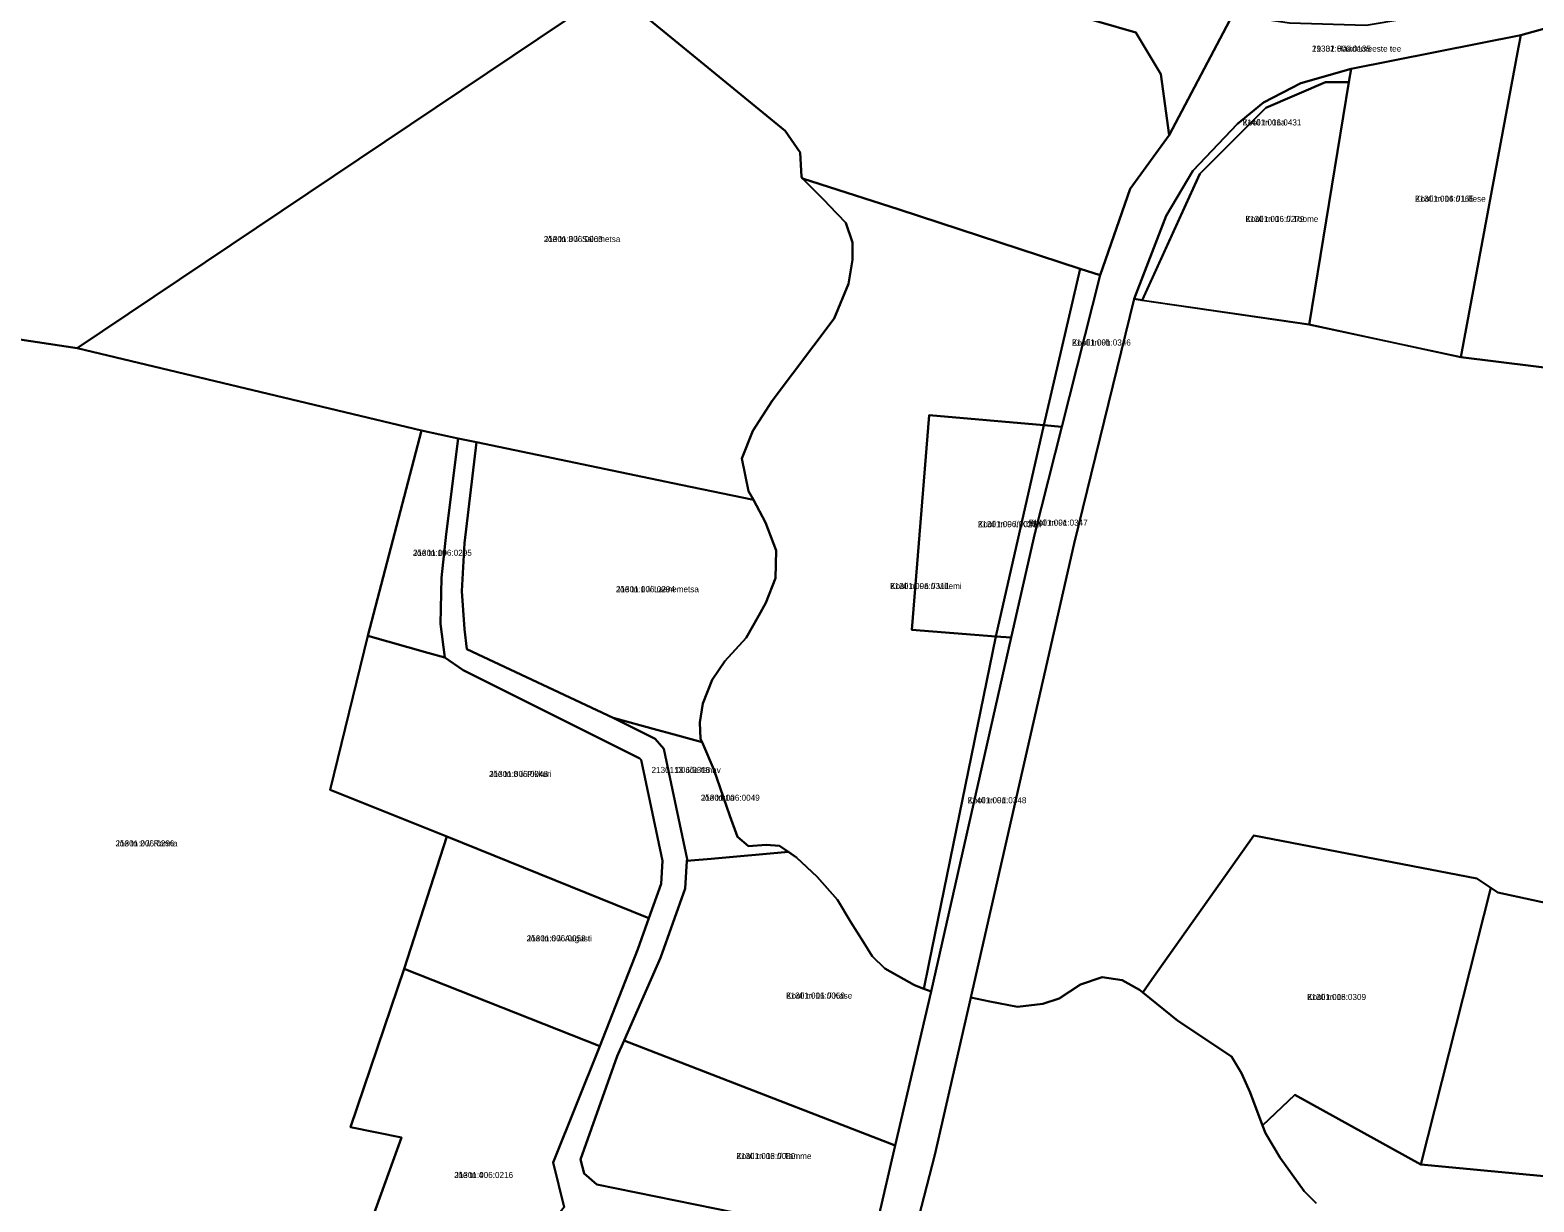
# Model space of a CAD drawing. Extents: x 520985 to 542706, y 6413723 to 6468993.
# Drawn here: x 528814.1 to 529184.5, y 6437370.3 to 6437658.9 of the extents above; entities that cross this region are included whole.
import ezdxf

# ---------------------------------------------------------------- set-up
doc = ezdxf.new("R2010")
doc.units = 0
for name, color, linetype in [('L_AADRESS', 7, 'Continuous'), ('PIIR', 7, 'Continuous'), ('TUNNUS', 7, 'Continuous')]:
    doc.layers.add(name, color=color, linetype=linetype)

msp = doc.modelspace()

# ---------------------------------------------------------------- linework, layer by layer
at = {"layer": 'PIIR'}
for points in [[(529022.94, 6437366.13), (529027.17, 6437384.16), (529036.06, 6437422.07), (529055.75, 6437509.24), (529061.56, 6437534.93), (529068.18, 6437561.14), (529077.63, 6437598.5), (529085.06, 6437619.76), (529094.63, 6437633.04), (529110.31, 6437662.71), (529124.29, 6437660.69), (529143.13, 6437660.13), (529162.25, 6437663.31), (529176.58, 6437665.99), (529231.94, 6437682.87)], [(528951.97, 6437665.27), (528825.68, 6437580.53), (528781.58, 6437587.19)], [(529068.18, 6437663.51), (529086.41, 6437658.27), (529092.59, 6437648.02), (529094.63, 6437633.04), (529085.06, 6437619.76), (529077.63, 6437598.5), (529072.76, 6437600.09), (529028.13, 6437614.73), (529004.35, 6437622.36), (529004.09, 6437622.7), (529003.78, 6437628.74), (529000.02, 6437634.04), (528962.09, 6437665.1)], [(529207.04, 6437664.8), (529181.26, 6437657.64), (529139.45, 6437649.35), (529127.06, 6437645.84), (529117.84, 6437641.01), (529111.48, 6437635.83), (529100.5, 6437624.23), (529093.87, 6437613.11), (529085.98, 6437592.65), (529071.25, 6437532.46), (529045.75, 6437420.61), (529036.91, 6437381.88), (529017.95, 6437308.4)], [(529110.31, 6437662.71), (529094.63, 6437633.04), (529092.59, 6437648.02), (529086.41, 6437658.27), (529068.18, 6437663.51)], [(529273.22, 6437425.26), (529175.58, 6437446.49), (529173.83, 6437447.63), (529170.46, 6437449.92), (529115.48, 6437460.49), (529090.38, 6437425.03), (529088.12, 6437421.84), (529087.32, 6437422.49), (529083.09, 6437424.88), (529078.15, 6437425.59), (529072.83, 6437423.84), (529067.56, 6437420.33), (529063.5, 6437419.05), (529057.25, 6437418.33), (529050.45, 6437419.63), (529045.75, 6437420.61), (529071.25, 6437532.46), (529085.98, 6437592.65), (529088, 6437592.36), (529129.01, 6437586.45), (529166.48, 6437578.36), (529202.94, 6437573.84)], [(528945.61, 6437368.99), (528942.95, 6437379.95), (528954.39, 6437408.63), (528963.75, 6437432.55), (528966.46, 6437440.14), (528969.5, 6437448.64), (528969.85, 6437454.26), (528964.59, 6437479.11), (528964.26, 6437479.49), (528920.74, 6437501.22), (528916.24, 6437504.33), (528915.15, 6437512.66), (528915.44, 6437523.97), (528916.57, 6437534.72), (528919.5, 6437558.33), (528924.06, 6437557.36), (528921.06, 6437532.5), (528920.43, 6437520.71), (528921.06, 6437511.35), (528921.65, 6437506.39), (528957.68, 6437489.5), (528968.01, 6437484.34), (528970.14, 6437481.86), (528975.9, 6437454.69), (528975.87, 6437454.26), (528975.43, 6437447.43), (528969.34, 6437430.34), (528960.4, 6437410.02), (528958.7, 6437406.14), (528949.67, 6437380.74), (528950.55, 6437377.24), (528953.69, 6437374.52), (529002.12, 6437364.71)], [(529017.95, 6437308.4), (529036.91, 6437381.88), (529045.75, 6437420.61), (529050.45, 6437419.63), (529057.25, 6437418.33), (529063.5, 6437419.05), (529067.56, 6437420.33), (529072.83, 6437423.84), (529078.15, 6437425.59), (529083.09, 6437424.88), (529087.32, 6437422.49), (529088.12, 6437421.84), (529096.74, 6437414.87), (529109.98, 6437406.05), (529112.49, 6437401.98), (529114.58, 6437397.18), (529117.66, 6437389.09), (529118.37, 6437387.22), (529121.96, 6437381.15), (529127.87, 6437372.94), (529130.87, 6437369.96)], [(529130.87, 6437369.96), (529127.87, 6437372.94), (529121.96, 6437381.15), (529118.37, 6437387.22), (529117.66, 6437389.09), (529125.57, 6437396.67), (529156.61, 6437379.48), (529244.98, 6437371.11), (529245.83, 6437371.03), (529171.7, 6437219.39)]]:
    msp.add_lwpolyline(points, dxfattribs=at)
for points in [[(528919.5, 6437558.33), (528910.48, 6437560.26), (528825.68, 6437580.53), (528951.97, 6437665.27), (528959.29, 6437670.18), (528962.09, 6437665.1), (529000.02, 6437634.04), (529003.78, 6437628.74), (529004.09, 6437622.7), (529004.35, 6437622.36), (529009.79, 6437616.82), (529010.88, 6437615.69), (529015, 6437611.4), (529016.65, 6437606.54), (529016.66, 6437602.33), (529015.63, 6437596.42), (529012.14, 6437587.86), (528996.85, 6437567.6), (528992.12, 6437560.18), (528989.42, 6437553.36), (528991.06, 6437545.29), (528992.23, 6437543.16), (528974.34, 6437546.88), (528924.06, 6437557.36)], [(529181.26, 6437657.64), (529207.04, 6437664.8), (529218.21, 6437668.23), (529217.82, 6437665.67), (529210.2, 6437615.42), (529202.94, 6437573.84), (529166.48, 6437578.36), (529180.71, 6437654.67)], [(529139.45, 6437649.35), (529181.26, 6437657.64), (529180.71, 6437654.67), (529166.48, 6437578.36), (529129.14, 6437586.29), (529138.91, 6437646.07)], [(529102.21, 6437623.47), (529087.98, 6437592.36), (529085.98, 6437592.65), (529093.87, 6437613.11), (529100.5, 6437624.23), (529111.48, 6437635.83), (529117.84, 6437641.01), (529127.06, 6437645.84), (529139.45, 6437649.35), (529138.91, 6437646.07), (529133.11, 6437646.05), (529118.48, 6437639.7)], [(529102.21, 6437623.47), (529118.48, 6437639.7), (529133.11, 6437646.05), (529138.91, 6437646.07), (529129.14, 6437586.29), (529087.95, 6437592.29)], [(529012.92, 6437444.63), (529007.91, 6437450.34), (529002.89, 6437455.13), (528998.65, 6437457.98), (528995.37, 6437458.18), (528991.03, 6437457.88), (528988.32, 6437460.22), (528986.4, 6437465.32), (528982.45, 6437476.73), (528979.58, 6437483.5), (528979.22, 6437484.35), (528979.07, 6437488.33), (528979.74, 6437493.06), (528982.05, 6437498.85), (528985.16, 6437503.45), (528990.47, 6437509.16), (528993.57, 6437514.73), (528995.3, 6437517.83), (528997.7, 6437523.88), (528997.84, 6437530.71), (528995.25, 6437537.57), (528992.23, 6437543.16), (528991.06, 6437545.29), (528989.42, 6437553.36), (528992.12, 6437560.18), (528996.85, 6437567.6), (529012.14, 6437587.86), (529015.63, 6437596.42), (529016.66, 6437602.33), (529016.65, 6437606.54), (529015, 6437611.4), (529010.88, 6437615.69), (529009.79, 6437616.82), (529004.35, 6437622.36), (529028.13, 6437614.73), (529072.76, 6437600.09), (529063.77, 6437561.61), (529035.54, 6437564.04), (529031.27, 6437511.14), (529051.96, 6437509.56), (529035.44, 6437428.81), (529034.19, 6437422.78), (529031.91, 6437423.66), (529024.57, 6437427.72), (529021.45, 6437430.77), (529019.38, 6437434.23), (529016.2, 6437439.13)], [(529072.76, 6437600.09), (529077.63, 6437598.5), (529068.18, 6437561.14), (529063.77, 6437561.61)], [(528763.29, 6437445.82), (528774.26, 6437528.12), (528775.61, 6437538.22), (528779.34, 6437571.35), (528780.07, 6437576.55), (528781.25, 6437584.93), (528781.58, 6437587.19), (528825.68, 6437580.53), (528910.48, 6437560.26), (528897.26, 6437509.7), (528888, 6437471.74), (528916.74, 6437460.23), (528906.2, 6437427.71), (528892.96, 6437388.69), (528905.53, 6437386.15), (528882.7, 6437322.88), (528881.29, 6437319.33), (528870.51, 6437323.67), (528753.51, 6437368.93), (528754.17, 6437373.73), (528758.2, 6437405.79)], [(529035.54, 6437564.04), (529063.77, 6437561.61), (529051.96, 6437509.56), (529031.27, 6437511.14)], [(528910.48, 6437560.26), (528919.5, 6437558.33), (528916.57, 6437534.72), (528915.44, 6437523.97), (528915.15, 6437512.66), (528916.24, 6437504.33), (528912.03, 6437505.52), (528897.26, 6437509.7)], [(529051.96, 6437509.56), (529063.77, 6437561.61), (529068.18, 6437561.14), (529061.56, 6437534.93), (529055.75, 6437509.24)], [(528957.68, 6437489.5), (528921.65, 6437506.39), (528921.06, 6437511.35), (528920.43, 6437520.71), (528921.06, 6437532.5), (528924.06, 6437557.36), (528974.34, 6437546.88), (528992.23, 6437543.16), (528995.25, 6437537.57), (528997.84, 6437530.71), (528997.7, 6437523.88), (528995.3, 6437517.83), (528993.57, 6437514.73), (528990.47, 6437509.16), (528985.16, 6437503.45), (528982.05, 6437498.85), (528979.74, 6437493.06), (528979.07, 6437488.33), (528979.22, 6437484.35), (528979.58, 6437483.5), (528970.95, 6437485.87), (528968.46, 6437486.54)], [(528888, 6437471.74), (528897.26, 6437509.7), (528912.03, 6437505.52), (528916.24, 6437504.33), (528920.74, 6437501.22), (528964.26, 6437479.49), (528964.59, 6437479.11), (528969.85, 6437454.26), (528969.5, 6437448.64), (528966.46, 6437440.14), (528966.05, 6437440.3), (528916.74, 6437460.23)], [(529051.96, 6437509.56), (529055.75, 6437509.24), (529036.06, 6437422.07), (529034.19, 6437422.78), (529035.44, 6437428.81)], [(528976.81, 6437454.34), (528975.87, 6437454.26), (528975.9, 6437454.69), (528970.14, 6437481.86), (528968.01, 6437484.34), (528957.68, 6437489.5), (528968.46, 6437486.54), (528970.95, 6437485.87), (528979.58, 6437483.5), (528982.45, 6437476.73), (528986.4, 6437465.32), (528988.32, 6437460.22), (528991.03, 6437457.88), (528995.37, 6437458.18), (528998.65, 6437457.98), (529000.89, 6437456.5), (528981.85, 6437454.79)], [(528916.74, 6437460.23), (528966.05, 6437440.3), (528966.46, 6437440.14), (528963.75, 6437432.55), (528954.39, 6437408.63), (528906.2, 6437427.71)], [(529114.58, 6437397.18), (529112.49, 6437401.98), (529109.98, 6437406.05), (529096.74, 6437414.87), (529088.12, 6437421.84), (529090.38, 6437425.03), (529115.48, 6437460.49), (529170.46, 6437449.92), (529173.83, 6437447.63), (529156.61, 6437379.48), (529125.57, 6437396.67), (529117.66, 6437389.09)], [(528960.4, 6437410.02), (528969.34, 6437430.34), (528975.43, 6437447.43), (528975.87, 6437454.26), (528976.81, 6437454.34), (528981.85, 6437454.79), (529000.89, 6437456.5), (529002.89, 6437455.13), (529007.91, 6437450.34), (529012.92, 6437444.63), (529016.2, 6437439.13), (529019.38, 6437434.23), (529021.45, 6437430.77), (529024.57, 6437427.72), (529031.91, 6437423.66), (529034.19, 6437422.78), (529036.06, 6437422.07), (529027.17, 6437384.16), (529025.27, 6437384.9), (528960.59, 6437409.95)], [(529173.83, 6437447.63), (529175.58, 6437446.49), (529273.22, 6437425.26), (529245.83, 6437371.03), (529244.98, 6437371.11), (529156.61, 6437379.48)], [(528954.39, 6437408.63), (528942.95, 6437379.95), (528945.61, 6437368.99), (528924.72, 6437342.7), (528910.25, 6437311.72), (528882.7, 6437322.88), (528905.53, 6437386.15), (528892.96, 6437388.69), (528906.2, 6437427.71)], [(528949.67, 6437380.74), (528958.7, 6437406.14), (528960.4, 6437410.02), (528960.59, 6437409.95), (529025.27, 6437384.9), (529027.17, 6437384.16), (529022.94, 6437366.13), (529019.14, 6437351.61), (529002.12, 6437364.71), (528953.69, 6437374.52), (528950.55, 6437377.24)]]:
    msp.add_lwpolyline(points, close=True, dxfattribs=at)

# ---------------------------------------------------------------- texts
at = {"layer": 'L_AADRESS'}
for s, p in [('19332 Häädemeeste tee', (529129.82, 6437653.57)), ('Kooli tn 16a', (529112.71, 6437635.39)), ('Kooli tn 14 // Lillese', (529155.2, 6437616.61)), ('Kooli tn 16 // Toome', (529113.43, 6437611.62)), ('Jõe tn 3 // Salumetsa', (528940.62, 6437606.67)), ('Kooli tn 9b', (529070.7, 6437581.19)), ('Kooli tn 9 // Kõrtsi', (529047.52, 6437536.45)), ('Kooli tn 9c', (529060.07, 6437536.82)), ('Jõe tn 10', (528908.38, 6437529.39)), ('Jõe tn 1 // Laanemetsa', (528958.39, 6437520.43)), ('Kooli tn 9a // Villemi', (529025.91, 6437521.21)), ('Jõe tn 8 // Pikkuri', (528927.13, 6437474.92)), ('2130113 Jõe tänav', (528967.14, 6437475.91)), ('Jõe tn 1a', (528979.29, 6437469.07)), ('Kooli tn 9d', (529044.97, 6437468.45)), ('Jõe tn 2 // Ranna', (528835.12, 6437457.82)), ('Jõe tn 6 // Augusti', (528936.4, 6437434.43)), ('Kooli tn 11 // Kase', (529000.29, 6437420.33)), ('Kooli tn 18', (529128.63, 6437419.99)), ('Kooli tn 13 // Tamme', (528988.04, 6437380.82)), ('Jõe tn 4', (528918.55, 6437376.15))]:
    msp.add_text(s, height=1.5, dxfattribs=at).set_placement(p)
at = {"layer": 'TUNNUS'}
for s, p in [('21301:006:0135', (529129.82, 6437653.57)), ('21401:001:0431', (529112.71, 6437635.39)), ('21301:006:0165', (529155.2, 6437616.61)), ('21301:006:0279', (529113.43, 6437611.62)), ('21301:006:0063', (528940.62, 6437606.67)), ('21401:001:0346', (529070.7, 6437581.19)), ('21301:006:0025', (529047.52, 6437536.45)), ('21401:001:0347', (529060.07, 6437536.82)), ('21301:006:0295', (528908.38, 6437529.39)), ('21301:006:0294', (528958.39, 6437520.43)), ('21301:006:0311', (529025.91, 6437521.21)), ('21301:006:0048', (528927.13, 6437474.92)), ('21301:006:0315', (528967.14, 6437475.91)), ('21301:006:0049', (528979.29, 6437469.07)), ('21401:001:0348', (529044.97, 6437468.45)), ('21301:006:0296', (528835.12, 6437457.82)), ('21301:006:0058', (528936.4, 6437434.43)), ('21301:006:0059', (529000.29, 6437420.33)), ('21301:006:0309', (529128.63, 6437419.99)), ('21301:006:0080', (528988.04, 6437380.82)), ('21301:006:0216', (528918.55, 6437376.15))]:
    msp.add_text(s, height=1.5, dxfattribs=at).set_placement(p)

doc.saveas('drawing.dxf')
